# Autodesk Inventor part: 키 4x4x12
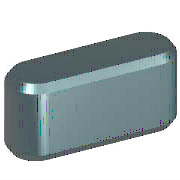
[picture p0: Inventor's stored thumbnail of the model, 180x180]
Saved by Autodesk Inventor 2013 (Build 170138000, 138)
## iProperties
IsCustomPart: 1
Created: 2012-02
Part Number: 키 4x4x12
Material: 강철, 연강
Description: 키 및 해당 키홈
Document SubType Name: Modeling
Standard: KS B 1311
Designer: mduedu
Standards Organization: KS
Language: ko-KR
Size Designation: 4 x 4 x 12
Categories: <MemberInstance><Categories><Category DisplayName="샤프트 부품" InternalName="7f7aeb1f-a693-4053-b835-cee3144e0d98" Mnemonic="SHFT"><Category DisplayName="키" Interna
Density: 1 g/cm^3
Author: mduedu
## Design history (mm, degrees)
workplane "Work Plane1"
workplane "Work Plane2"
sketch "스케치1"
  geometry: L1 (2, 2)-(10, 2); L2 (10, -2)-(2, -2); L3 (0, 9.4)-(0, -7.4) reference; L4 (-5, 0)-(30, 0) reference; L5 (12, 0)-(12, 7); A1 r 2 centre (2, 0) between (2, 2) and (2, -2); A2 r 2 centre (10, 0) between (10, -2) and (10, 2)
  constraints: 6 end point, 5 point on circle, 4 tangent, 3 point on line, 2 centre point, 1 horizontal, 1 parallel, 1 perpendicular
  dimensions: "d0" = 2 radius of A1 (= 0.5 x PB); "d13" = 2 radius of A2 (= 0.5 x PB); "d14" = 12 distance between parallel lines of L5 L3 (= NLG)
extrude "본체1" new body sketch "스케치1" taper "d3" = 0 deg; stored distance "d4" = 10
workplane "Work Plane3"
body "Solid1"
chamfer "모따기1" distance "d8" = 0.25 (= PHH); stored, may be unused: second distance "d9" = 0.25 (= PHH), angle "d15" = 45 deg
other parameters: "d1" = -2.5 (= -PNT), "d2" = 1.5 (= PH - PNT), "NLG" = 12 [user parameter; used in 3 equation terms], "PB" = 4 [user parameter; used in 2 equation terms], "PNT" = 2.5 [user parameter; used in 2 equation terms], "PH" = 4 [user parameter; used in 1 equation term], "PHH" = 0.25 [user parameter; used in 2 equation terms], "d10" = 0, "d16" = 0, "d17" = 0, "d18" = 0, "PLB2" = 12 (= NLG) [user parameter], "WDMAX" = 12 [user parameter], "PLB1" = 12 (= NLG) [user parameter], "RR" = 0.08 [user parameter], "PUEB" = 1.8 [user parameter]
